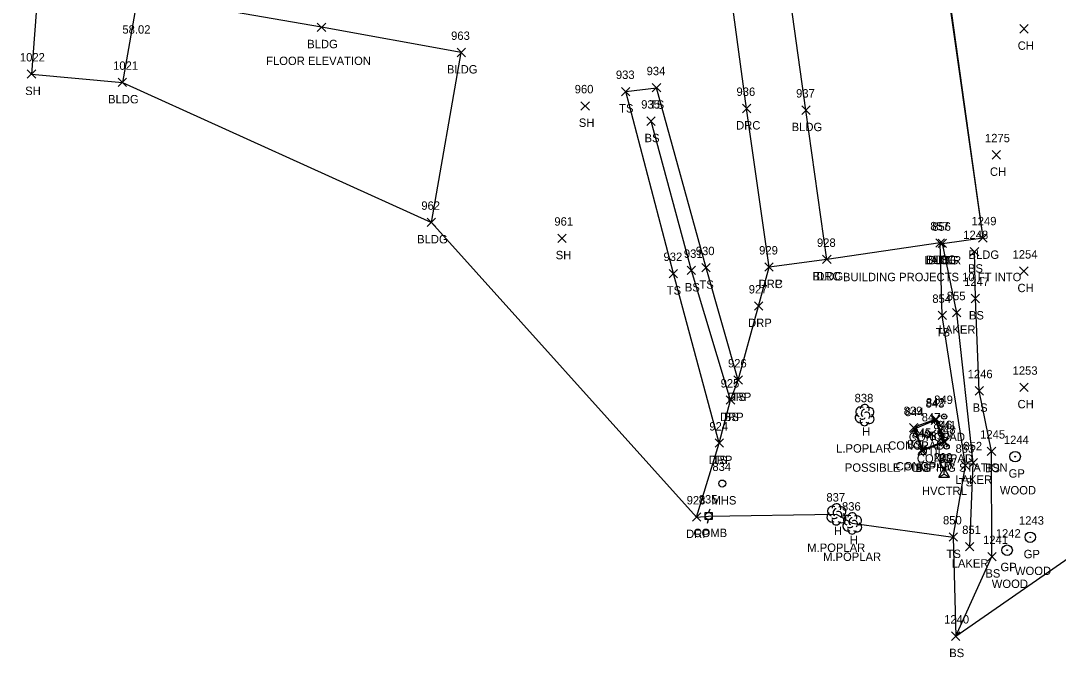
# Model space of a CAD drawing. Extents: x 1716490 to 1717645, y 888034 to 890004.
# Drawn here: x 1716665.3 to 1716912.5, y 888034 to 888185.6 of the extents above; entities that cross this region are included whole.
import ezdxf

# ---------------------------------------------------------------- set-up
doc = ezdxf.new("R2010")
doc.units = 0
for name, color, linetype in [('C_A', 7, 'Continuous'), ('C_C', 7, 'Continuous'), ('C_I', 7, 'Continuous'), ('CPSM', 7, 'Continuous'), ('L_A', 7, 'Continuous'), ('L_C', 7, 'Continuous'), ('L_I', 7, 'Continuous'), ('L_TIC', 7, 'Continuous'), ('LAWE', 7, 'Continuous'), ('LBC', 7, 'Continuous'), ('LELB', 7, 'Continuous'), ('LS', 7, 'Continuous'), ('LSOGP', 7, 'Continuous'), ('LTD', 7, 'Continuous'), ('R_A', 7, 'Continuous'), ('R_C', 7, 'Continuous'), ('R_I', 7, 'Continuous'), ('R_TIC', 7, 'Continuous'), ('RDP', 7, 'Continuous'), ('RGP', 7, 'Continuous'), ('U_A', 7, 'Continuous'), ('U_C', 7, 'Continuous'), ('U_I', 7, 'Continuous'), ('UDEFAULT', 7, 'Continuous'), ('UP', 7, 'Continuous'), ('USMH', 7, 'Continuous'), ('UWV', 7, 'Continuous')]:
    doc.layers.add(name, color=color, linetype=linetype)

msp = doc.modelspace()

# ---------------------------------------------------------------- linework, layer by layer
at = {"layer": 'CPSM'}
for p, q in [((1716884.08, 888076.89), (1716885.33, 888079.06)), ((1716884.08, 888076.89), (1716885.33, 888079.06)), ((1716884.08, 888076.89), (1716885.33, 888079.06)), ((1716884.08, 888076.89), (1716885.33, 888077.61)), ((1716884.08, 888076.89), (1716885.33, 888077.61)), ((1716884.08, 888076.89), (1716885.33, 888077.61)), ((1716884.08, 888076.89), (1716886.58, 888076.89)), ((1716884.08, 888076.89), (1716886.58, 888076.89)), ((1716884.08, 888076.89), (1716886.58, 888076.89)), ((1716886.58, 888076.89), (1716885.33, 888079.06)), ((1716885.33, 888077.61), (1716885.33, 888079.06)), ((1716886.58, 888076.89), (1716885.33, 888079.06)), ((1716885.33, 888077.61), (1716885.33, 888079.06)), ((1716886.58, 888076.89), (1716885.33, 888079.06)), ((1716885.33, 888077.61), (1716885.33, 888079.06)), ((1716885.33, 888077.61), (1716885.33, 888077.61)), ((1716885.33, 888077.61), (1716886.58, 888076.89)), ((1716885.33, 888077.61), (1716885.33, 888077.61)), ((1716885.33, 888077.61), (1716886.58, 888076.89)), ((1716885.33, 888077.61), (1716885.33, 888077.61)), ((1716885.33, 888077.61), (1716886.58, 888076.89))]:
    msp.add_line(p, q, dxfattribs=at)
at = {"layer": 'L_TIC'}
for points in [[(1716735.98, 888183.04), (1716737.98, 888185.04)], [(1716737.98, 888183.04), (1716735.98, 888185.04)], [(1716903.35, 888182.66), (1716905.35, 888184.66)], [(1716905.35, 888182.66), (1716903.35, 888184.66)], [(1716769.27, 888177.02), (1716771.27, 888179.02)], [(1716771.27, 888177.02), (1716769.27, 888179.02)], [(1716666.9, 888171.89), (1716668.9, 888173.89)], [(1716668.9, 888171.89), (1716666.9, 888173.89)], [(1716688.55, 888169.9), (1716690.55, 888171.9)], [(1716690.55, 888169.9), (1716688.55, 888171.9)], [(1716808.47, 888167.72), (1716810.47, 888169.72)], [(1716810.47, 888167.72), (1716808.47, 888169.72)], [(1716815.79, 888168.62), (1716817.79, 888170.62)], [(1716817.79, 888168.62), (1716815.79, 888170.62)], [(1716815.79, 888168.62), (1716817.79, 888170.62)], [(1716817.79, 888168.62), (1716815.79, 888170.62)], [(1716798.8, 888164.3), (1716800.8, 888166.3)], [(1716800.8, 888164.3), (1716798.8, 888166.3)], [(1716851.4, 888163.29), (1716853.4, 888165.29)], [(1716853.4, 888163.29), (1716851.4, 888165.29)], [(1716814.5, 888160.66), (1716816.5, 888162.66)], [(1716816.5, 888160.66), (1716814.5, 888162.66)], [(1716896.73, 888152.64), (1716898.73, 888154.64)], [(1716898.73, 888152.64), (1716896.73, 888154.64)], [(1716762.17, 888136.56), (1716764.17, 888138.56)], [(1716764.17, 888136.56), (1716762.17, 888138.56)], [(1716793.29, 888132.78), (1716795.29, 888134.78)], [(1716795.29, 888132.78), (1716793.29, 888134.78)], [(1716893.53, 888132.87), (1716895.53, 888134.87)], [(1716895.53, 888132.87), (1716893.53, 888134.87)], [(1716883.37, 888131.67), (1716885.37, 888133.67)], [(1716885.37, 888131.67), (1716883.37, 888133.67)], [(1716883.37, 888131.67), (1716885.37, 888133.67)], [(1716885.37, 888131.67), (1716883.37, 888133.67)], [(1716883.89, 888131.55), (1716885.89, 888133.55)], [(1716885.89, 888131.55), (1716883.89, 888133.55)], [(1716883.89, 888131.55), (1716885.89, 888133.55)], [(1716885.89, 888131.55), (1716883.89, 888133.55)], [(1716883.89, 888131.55), (1716885.89, 888133.55)], [(1716885.89, 888131.55), (1716883.89, 888133.55)], [(1716891.55, 888129.59), (1716893.55, 888131.59)], [(1716893.55, 888129.59), (1716891.55, 888131.59)], [(1716856.37, 888127.73), (1716858.37, 888129.73)], [(1716858.37, 888127.73), (1716856.37, 888129.73)], [(1716819.82, 888124.36), (1716821.82, 888126.36)], [(1716821.82, 888124.36), (1716819.82, 888126.36)], [(1716824.1, 888125.11), (1716826.1, 888127.11)], [(1716826.1, 888125.11), (1716824.1, 888127.11)], [(1716827.6, 888125.76), (1716829.6, 888127.76)], [(1716829.6, 888125.76), (1716827.6, 888127.76)], [(1716903.3, 888124.94), (1716905.3, 888126.94)], [(1716905.3, 888124.94), (1716903.3, 888126.94)], [(1716891.76, 888118.43), (1716893.76, 888120.43)], [(1716893.76, 888118.43), (1716891.76, 888120.43)], [(1716883.87, 888114.39), (1716885.87, 888116.39)], [(1716885.87, 888114.39), (1716883.87, 888116.39)], [(1716887.31, 888115.03), (1716889.31, 888117.03)], [(1716889.31, 888115.03), (1716887.31, 888117.03)], [(1716835.24, 888099.01), (1716837.24, 888101.01)], [(1716837.24, 888099.01), (1716835.24, 888101.01)], [(1716903.31, 888097.27), (1716905.31, 888099.27)], [(1716905.31, 888097.27), (1716903.31, 888099.27)], [(1716892.67, 888096.44), (1716894.67, 888098.44)], [(1716894.67, 888096.44), (1716892.67, 888098.44)], [(1716833.42, 888094.23), (1716835.42, 888096.23)], [(1716835.42, 888094.23), (1716833.42, 888096.23)], [(1716882.34, 888089.71), (1716884.34, 888091.71)], [(1716884.34, 888089.71), (1716882.34, 888091.71)], [(1716877.04, 888087.67), (1716879.04, 888089.67)], [(1716879.04, 888087.67), (1716877.04, 888089.67)], [(1716877.33, 888087.41), (1716879.33, 888089.41)], [(1716879.33, 888087.41), (1716877.33, 888089.41)], [(1716882.26, 888089.45), (1716884.26, 888091.45)], [(1716884.26, 888089.45), (1716882.26, 888091.45)], [(1716830.74, 888083.98), (1716832.74, 888085.98)], [(1716832.74, 888083.98), (1716830.74, 888085.98)], [(1716879.12, 888082.48), (1716881.12, 888084.48)], [(1716881.12, 888082.48), (1716879.12, 888084.48)], [(1716884.16, 888084.33), (1716886.16, 888086.33)], [(1716886.16, 888084.33), (1716884.16, 888086.33)], [(1716884.52, 888084.28), (1716886.52, 888086.28)], [(1716886.52, 888084.28), (1716884.52, 888086.28)], [(1716879.04, 888082.11), (1716881.04, 888084.11)], [(1716881.04, 888082.11), (1716879.04, 888084.11)], [(1716895.59, 888082.05), (1716897.59, 888084.05)], [(1716897.59, 888082.05), (1716895.59, 888084.05)], [(1716889.38, 888078.69), (1716891.38, 888080.69)], [(1716891.38, 888078.69), (1716889.38, 888080.69)], [(1716891.26, 888079.28), (1716893.26, 888081.28)], [(1716893.26, 888079.28), (1716891.26, 888081.28)], [(1716886.48, 888061.62), (1716888.48, 888063.62)], [(1716888.48, 888061.62), (1716886.48, 888063.62)], [(1716890.4, 888059.34), (1716892.4, 888061.34)], [(1716892.4, 888059.34), (1716890.4, 888061.34)], [(1716895.7, 888056.95), (1716897.7, 888058.95)], [(1716897.7, 888056.95), (1716895.7, 888058.95)], [(1716887.08, 888038.01), (1716889.08, 888040.01)], [(1716889.08, 888038.01), (1716887.08, 888040.01)]]:
    msp.add_lwpolyline(points, dxfattribs=at)
at = {"layer": 'LAWE'}
msp.add_lwpolyline([(1716891.4, 888060.34), (1716892.26, 888080.28), (1716888.31, 888116.03), (1716884.89, 888132.55)], dxfattribs=at)
at = {"layer": 'LBC'}
for points in [[(1716884.89, 888132.55), (1716884.37, 888132.67), (1716857.37, 888128.73), (1716852.4, 888164.29), (1716847.83, 888196.87), (1716876.38, 888200.84), (1716883.53, 888201.86), (1716883.7, 888201.99), (1716884.83, 888201.98)], [(1716884.83, 888201.98), (1716894.53, 888133.87)], [(1716763.17, 888137.56), (1716770.27, 888178.02), (1716736.98, 888184.04), (1716693.25, 888191.71), (1716689.55, 888170.9)], [(1716884.89, 888132.55), (1716894.53, 888133.87)]]:
    msp.add_lwpolyline(points, dxfattribs=at)
at = {"layer": 'LELB'}
for points in [[(1716885.09, 888201.63), (1716894.53, 888133.87)], [(1716831.74, 888084.98), (1716820.82, 888125.36), (1716809.47, 888168.72), (1716816.79, 888169.62)], [(1716836.24, 888100.01), (1716828.6, 888126.76), (1716816.79, 888169.62)], [(1716834.42, 888095.23), (1716825.1, 888126.11), (1716815.5, 888161.66)], [(1716887.48, 888062.62), (1716890.38, 888079.69), (1716884.87, 888115.39), (1716884.37, 888132.67)], [(1716888.08, 888039.01), (1716896.7, 888057.95), (1716896.59, 888083.05), (1716893.67, 888097.44), (1716892.76, 888119.43), (1716892.55, 888130.59)], [(1716878.04, 888088.67), (1716880.04, 888083.11), (1716885.52, 888085.28), (1716883.34, 888090.71)], [(1716883.34, 888090.71), (1716878.04, 888088.67)]]:
    msp.add_lwpolyline(points, dxfattribs=at)
at = {"layer": 'LS'}
for points in [[(1716883.26, 888090.45), (1716878.33, 888088.41), (1716880.12, 888083.48), (1716885.16, 888085.33)], [(1716885.16, 888085.33), (1716883.26, 888090.45)]]:
    msp.add_lwpolyline(points, dxfattribs=at)
at = {"layer": 'LSOGP'}
msp.add_lwpolyline([(1716669.38, 888192.85), (1716667.9, 888172.89), (1716689.55, 888170.91), (1716763.17, 888137.56), (1716826.34, 888067.38), (1716829.21, 888067.6), (1716859.62, 888068.07), (1716863.39, 888065.91), (1716887.49, 888062.62), (1716888.08, 888039.01), (1716915.87, 888058.3)], dxfattribs=at)
at = {"layer": 'LTD'}
for p, q in [((1716866.34, 888091.72), (1716866.34, 888091.72)), ((1716866.34, 888091.72), (1716866.34, 888091.72)), ((1716859.63, 888068.07), (1716859.63, 888068.07)), ((1716859.63, 888068.07), (1716859.63, 888068.07)), ((1716863.39, 888065.91), (1716863.39, 888065.91)), ((1716863.39, 888065.91), (1716863.39, 888065.91))]:
    msp.add_line(p, q, dxfattribs=at)
for centre in [(1716866.39, 888093.15), (1716859.67, 888069.51), (1716863.44, 888067.34)]:
    msp.add_arc(centre, 1.05, 335.5272, 180.9563, dxfattribs=at)
for centre, major_axis, ratio, start_param, end_param in [((1716865.26, 888091.01), (0.58, -1.04), 0.959034, 3.141593, 6.283185), ((1716865.55, 888092.38), (1.21, -0.51), 0.895232, 1.570796, 4.712389), ((1716866.13, 888092.17), (-0.208, -0.792), 0.645439, 3.141593, 6.283185), ((1716866.84, 888091.55), (-0.5, 0.667), 0.989748, 3.141593, 6.283185), ((1716867.34, 888090.88), (-1.09, 0.79), 0.841452, 1.570796, 4.712389), ((1716867.38, 888092.3), (-1.14, -0.48), 0.949671, 1.570796, 4.712389), ((1716866.34, 888090.22), (0.26, 1.06), 0.942809, 1.570796, 4.712389), ((1716865.88, 888090.97), (-0.625, -0.083), 0.423636, 0, 3.141593), ((1716858.83, 888068.74), (1.21, -0.51), 0.895232, 1.570796, 4.712389), ((1716860.67, 888068.66), (-1.14, -0.48), 0.949671, 1.570796, 4.712389), ((1716858.54, 888067.36), (0.58, -1.04), 0.959034, 3.141593, 6.283185), ((1716859.17, 888067.32), (-0.625, -0.083), 0.423636, 0, 3.141593), ((1716859.42, 888068.53), (-0.208, -0.792), 0.645439, 3.141593, 6.283185), ((1716860.13, 888067.91), (-0.5, 0.667), 0.989748, 3.141593, 6.283185), ((1716860.63, 888067.24), (-1.09, 0.79), 0.841452, 1.570796, 4.712389), ((1716862.6, 888066.58), (1.21, -0.51), 0.895232, 1.570796, 4.712389), ((1716863.18, 888066.37), (-0.208, -0.792), 0.645439, 3.141593, 6.283185), ((1716864.43, 888066.49), (-1.14, -0.48), 0.949671, 1.570796, 4.712389), ((1716859.63, 888066.57), (0.26, 1.06), 0.942809, 1.570796, 4.712389), ((1716862.31, 888065.2), (0.58, -1.04), 0.959034, 3.141593, 6.283185), ((1716863.39, 888064.41), (0.26, 1.06), 0.942809, 1.570796, 4.712389), ((1716862.93, 888065.16), (-0.625, -0.083), 0.423636, 0, 3.141593), ((1716863.89, 888065.74), (-0.5, 0.667), 0.989748, 3.141593, 6.283185), ((1716864.39, 888065.08), (-1.09, 0.79), 0.841452, 1.570796, 4.712389)]:
    msp.add_ellipse(centre, major_axis=major_axis, ratio=ratio, start_param=start_param, end_param=end_param, dxfattribs=at)
at = {"layer": 'R_TIC'}
for points in [[(1716837.26, 888163.68), (1716839.26, 888165.68)], [(1716839.26, 888163.68), (1716837.26, 888165.68)], [(1716856.37, 888127.73), (1716858.37, 888129.73)], [(1716858.37, 888127.73), (1716856.37, 888129.73)], [(1716842.61, 888125.91), (1716844.61, 888127.91)], [(1716844.61, 888125.91), (1716842.61, 888127.91)], [(1716842.61, 888125.91), (1716844.61, 888127.91)], [(1716844.61, 888125.91), (1716842.61, 888127.91)], [(1716840.12, 888116.63), (1716842.12, 888118.63)], [(1716842.12, 888116.63), (1716840.12, 888118.63)], [(1716835.24, 888099.01), (1716837.24, 888101.01)], [(1716837.24, 888099.01), (1716835.24, 888101.01)], [(1716833.42, 888094.23), (1716835.42, 888096.23)], [(1716835.42, 888094.23), (1716833.42, 888096.23)], [(1716830.74, 888083.98), (1716832.74, 888085.98)], [(1716832.74, 888083.98), (1716830.74, 888085.98)], [(1716825.34, 888066.38), (1716827.34, 888068.38)], [(1716827.34, 888066.38), (1716825.34, 888068.38)]]:
    msp.add_lwpolyline(points, dxfattribs=at)
at = {"layer": 'RDP'}
for points in [[(1716857.37, 888128.73), (1716843.61, 888126.91), (1716838.26, 888164.68), (1716834.18, 888194.7), (1716847.83, 888196.87)], [(1716826.34, 888067.38), (1716831.74, 888084.98), (1716834.42, 888095.23), (1716836.24, 888100.01), (1716841.12, 888117.63), (1716843.61, 888126.91)]]:
    msp.add_lwpolyline(points, dxfattribs=at)
at = {"layer": 'RGP'}
for p, q in [((1716902.23, 888081.76), (1716902.23, 888081.76)), ((1716905.83, 888062.56), (1716905.83, 888062.56)), ((1716900.31, 888059.48), (1716900.31, 888059.48))]:
    msp.add_line(p, q, dxfattribs=at)
for centre, radius in [((1716902.23, 888081.76), 1.25), ((1716902.23, 888081.76), 0.0833), ((1716905.83, 888062.56), 1.25), ((1716905.83, 888062.56), 0.0833), ((1716900.31, 888059.48), 1.25), ((1716900.31, 888059.48), 0.0833)]:
    msp.add_circle(centre, radius, dxfattribs=at)
at = {"layer": 'UDEFAULT'}
for points in [[(1716881.33, 888086.16), (1716883.33, 888088.16)], [(1716883.33, 888086.16), (1716881.33, 888088.16)]]:
    msp.add_lwpolyline(points, dxfattribs=at)
at = {"layer": 'UP'}
for p, q in [((1716828.38, 888066.77), (1716828.38, 888068.43)), ((1716828.38, 888068.43), (1716830.04, 888068.43)), ((1716829.46, 888069.27), (1716829.21, 888068.43)), ((1716829.21, 888067.6), (1716829.21, 888067.6)), ((1716830.04, 888068.43), (1716830.04, 888066.77)), ((1716830.04, 888066.77), (1716828.38, 888066.77)), ((1716828.96, 888065.93), (1716829.21, 888066.77))]:
    msp.add_line(p, q, dxfattribs=at)
msp.add_circle((1716829.21, 888067.6), 0.833, dxfattribs=at)
at = {"layer": 'USMH'}
for p, q in [((1716832.46, 888075.36), (1716832.46, 888075.36)), ((1716833.29, 888075.36), (1716833.29, 888075.36))]:
    msp.add_line(p, q, dxfattribs=at)
msp.add_circle((1716832.46, 888075.36), 0.833, dxfattribs=at)
at = {"layer": 'UWV'}
for centre, radius in [((1716885.31, 888091.31), 0.625), ((1716885.31, 888091.31), 0.0833), ((1716885.91, 888084.17), 0.625), ((1716885.91, 888084.17), 0.0833)]:
    msp.add_circle(centre, radius, dxfattribs=at)

# ---------------------------------------------------------------- texts
at = {"layer": 'C_A'}
msp.add_text('HVCTRL', height=2, dxfattribs=at).set_placement((1716880.03, 888072.61))
msp.add_text('HVCTRL', height=2, dxfattribs=at).set_placement((1716880.03, 888072.61))
msp.add_text('HVCTRL', height=2, dxfattribs=at).set_placement((1716880.03, 888072.61))
at = {"layer": 'C_C'}
msp.add_text('58.02', height=2, dxfattribs=at).set_placement((1716689.55, 888182.51))
at = {"layer": 'C_I'}
msp.add_text('200', height=2, dxfattribs=at).set_placement((1716882.81, 888080.61))
msp.add_text('200', height=2, dxfattribs=at).set_placement((1716882.81, 888080.61))
msp.add_text('200', height=2, dxfattribs=at).set_placement((1716882.81, 888080.61))
at = {"layer": 'L_A'}
for s, p in [('BLDG', (1716733.57, 888179.04)), ('CH', (1716902.84, 888178.66)), ('BLDG', (1716766.86, 888173.02)), ('SH', (1716666.39, 888167.89)), ('BLDG', (1716686.14, 888165.9)), ('TS', (1716815.2, 888164.62)), ('TS', (1716815.2, 888164.62)), ('TS', (1716807.88, 888163.72)), ('SH', (1716798.29, 888160.3)), ('BLDG', (1716848.99, 888159.29)), ('BS', (1716813.94, 888156.66)), ('CH', (1716896.22, 888148.64)), ('BLDG', (1716759.76, 888132.56)), ('SH', (1716792.78, 888128.78)), ('LAKER', (1716880.6, 888127.55)), ('BLDG', (1716880.96, 888127.67)), ('BLDG', (1716881.48, 888127.55)), ('BLDG', (1716881.48, 888127.55)), ('TS', (1716882.78, 888127.67)), ('BLDG', (1716891.12, 888128.87)), ('BS', (1716891, 888125.59)), ('BLDG', (1716853.97, 888123.73)), ('TS', (1716819.23, 888120.36)), ('BS', (1716823.54, 888121.11)), ('TS', (1716827.01, 888121.76)), ('CH', (1716902.79, 888120.94)), ('BS', (1716891.21, 888114.43)), ('TS', (1716883.28, 888110.39)), ('LAKER', (1716884.01, 888111.03)), ('TS', (1716834.65, 888095.01)), ('BS', (1716892.11, 888092.44)), ('CH', (1716902.8, 888093.27)), ('BS', (1716832.86, 888090.23)), ('H', (1716865.77, 888086.72)), ('CONCPAD', (1716876.9, 888085.45)), ('BS', (1716881.78, 888085.71)), ('CONCPAD', (1716871.98, 888083.41)), ('BS', (1716876.48, 888083.67)), ('TS', (1716830.15, 888079.98)), ('CONCPAD', (1716878.81, 888080.33)), ('BS', (1716883.96, 888080.28)), ('CONCPAD', (1716873.77, 888078.48)), ('BS', (1716878.48, 888078.11)), ('BS', (1716895.03, 888078.05)), ('LAKER', (1716887.97, 888075.28)), ('TS', (1716888.79, 888074.69)), ('H', (1716859.06, 888063.07)), ('H', (1716862.83, 888060.91)), ('TS', (1716885.89, 888057.62)), ('LAKER', (1716887.11, 888055.34)), ('BS', (1716895.14, 888052.95)), ('BS', (1716886.52, 888034.01))]:
    msp.add_text(s, height=2, dxfattribs=at).set_placement(p)
at = {"layer": 'L_C'}
for s, p in [('FLOOR ELEVATION', (1716723.79, 888175.04)), ('BUILDING PROJECTS 10 FT INTO', (1716861.21, 888123.55)), ('L.POPLAR', (1716859.59, 888082.72)), ('M.POPLAR', (1716852.7, 888059.07)), ('M.POPLAR', (1716856.47, 888056.91))]:
    msp.add_text(s, height=2, dxfattribs=at).set_placement(p)
at = {"layer": 'L_I'}
for s, p in [('963', (1716767.86, 888181.02)), ('1022', (1716665.13, 888175.89)), ('1021', (1716687.34, 888173.9)), ('933', (1716807.11, 888171.72)), ('934', (1716814.43, 888172.62)), ('934', (1716814.43, 888172.62)), ('960', (1716797.3, 888168.3)), ('937', (1716850.04, 888167.29)), ('935', (1716813.14, 888164.66)), ('1275', (1716895.04, 888156.64)), ('962', (1716760.76, 888140.56)), ('961', (1716792.45, 888136.78)), ('1249', (1716891.83, 888136.87)), ('857', (1716882.01, 888135.67)), ('857', (1716882.01, 888135.67)), ('856', (1716882.47, 888135.55)), ('856', (1716882.47, 888135.55)), ('856', (1716882.47, 888135.55)), ('928', (1716855.01, 888131.73)), ('1248', (1716889.86, 888133.59)), ('930', (1716826.15, 888129.76)), ('932', (1716818.46, 888128.36)), ('931', (1716823.31, 888129.11)), ('1254', (1716901.61, 888128.94)), ('1247', (1716890.07, 888122.43)), ('854', (1716882.5, 888118.39)), ('855', (1716885.94, 888119.03)), ('926', (1716833.82, 888103.01)), ('1246', (1716890.92, 888100.44)), ('1253', (1716901.62, 888101.27)), ('925', (1716832.06, 888098.23)), ('838', (1716863.98, 888094.72)), ('843', (1716880.9, 888093.45)), ('842', (1716880.98, 888093.71)), ('839', (1716875.67, 888091.67)), ('844', (1716875.97, 888091.41)), ('924', (1716829.38, 888087.98)), ('846', (1716882.74, 888088.33)), ('841', (1716883.73, 888088.28)), ('840', (1716877.59, 888086.11)), ('845', (1716877.76, 888086.48)), ('1245', (1716893.89, 888086.05)), ('853', (1716888.02, 888082.69)), ('852', (1716889.9, 888083.28)), ('837', (1716857.26, 888071.07)), ('836', (1716860.98, 888068.91)), ('850', (1716885.04, 888065.62)), ('851', (1716889.61, 888063.34)), ('1241', (1716894.58, 888060.95)), ('1240', (1716885.3, 888042.01))]:
    msp.add_text(s, height=2, dxfattribs=at).set_placement(p)
at = {"layer": 'R_A'}
for s, p in [('DRC', (1716835.75, 888159.68)), ('DRC', (1716841.1, 888121.91)), ('DRP', (1716841.1, 888121.91)), ('DRC', (1716854.86, 888123.73)), ('DRP', (1716838.61, 888112.63)), ('DRP', (1716833.72, 888095.01)), ('DRP', (1716831.91, 888090.23)), ('DRP', (1716829.23, 888079.98)), ('GP', (1716900.67, 888076.76)), ('DRP', (1716823.83, 888062.38)), ('GP', (1716904.26, 888057.56)), ('GP', (1716898.74, 888054.48))]:
    msp.add_text(s, height=2, dxfattribs=at).set_placement(p)
at = {"layer": 'R_C'}
for p in [(1716898.59, 888072.76), (1716902.18, 888053.56), (1716896.66, 888050.48)]:
    msp.add_text('WOOD', height=2, dxfattribs=at).set_placement(p)
at = {"layer": 'R_I'}
for s, p in [('936', (1716835.84, 888167.68)), ('928', (1716855.01, 888131.73)), ('929', (1716841.24, 888129.91)), ('929', (1716841.24, 888129.91)), ('927', (1716838.76, 888120.63)), ('926', (1716833.82, 888103.01)), ('925', (1716832.06, 888098.23)), ('924', (1716829.38, 888087.98)), ('1244', (1716899.54, 888084.76)), ('923', (1716823.97, 888070.38)), ('1243', (1716903.14, 888065.56)), ('1242', (1716897.61, 888062.48))]:
    msp.add_text(s, height=2, dxfattribs=at).set_placement(p)
at = {"layer": 'U_A'}
for s, p in [('GV', (1716883.71, 888086.31)), ('UTIL', (1716879.49, 888082.16)), ('GV', (1716884.31, 888079.17)), ('MHS', (1716829.88, 888070.36)), ('COMB', (1716825.6, 888062.6))]:
    msp.add_text(s, height=2, dxfattribs=at).set_placement(p)
at = {"layer": 'U_C'}
msp.add_text('POSSIBLE PUMPING STATION', height=2, dxfattribs=at).set_placement((1716861.66, 888078.16))
at = {"layer": 'U_I'}
for s, p in [('849', (1716882.93, 888094.31)), ('847', (1716879.96, 888090.16)), ('848', (1716883.55, 888087.17)), ('834', (1716830.1, 888078.36)), ('835', (1716826.85, 888070.6))]:
    msp.add_text(s, height=2, dxfattribs=at).set_placement(p)

doc.saveas('drawing.dxf')
